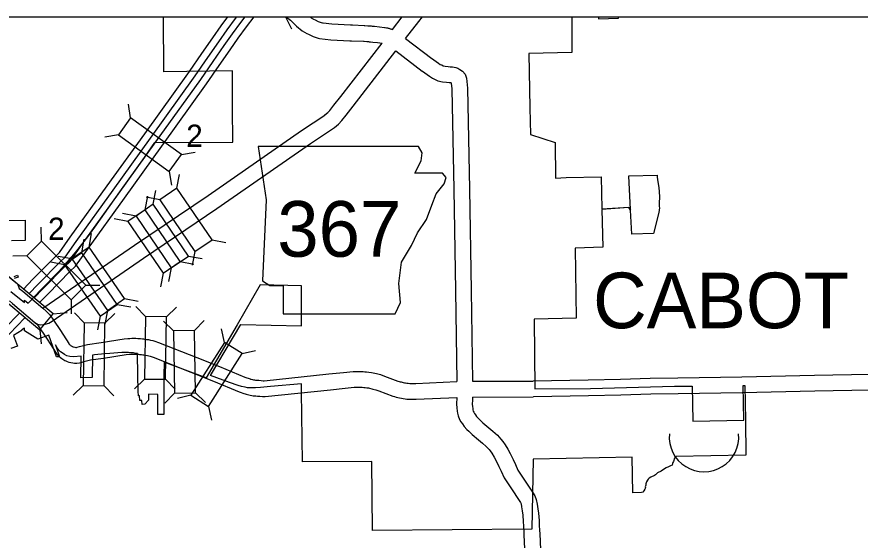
# Model space of a CAD drawing. Extents: x 1127717 to 1741049, y 2026793 to 2244711.
# Drawn here: x 1248173 to 1256180, y 2150676 to 2155644 of the extents above; entities that cross this region are included whole.
import ezdxf

# ---------------------------------------------------------------- set-up
doc = ezdxf.new("R2010")
doc.units = 0
for name, color, linetype in [('1', 7, 'Continuous'), ('10', 7, 'Continuous'), ('15', 7, 'Continuous'), ('20', 7, 'Continuous'), ('21', 7, 'Continuous'), ('27', 7, 'Continuous'), ('6', 7, 'Continuous')]:
    doc.layers.add(name, color=color, linetype=linetype)

msp = doc.modelspace()

# ---------------------------------------------------------------- linework, layer by layer
at = {"layer": '1'}
msp.add_lwpolyline([(1238438.2, 2155644.2), (1269451.6, 2155644.2), (1269451.6, 2123596.1), (1238438.2, 2123596.1)], close=True, dxfattribs=at)
at = {"layer": '10'}
for points in [[(1250731.1, 2155644.2), (1250771.9, 2155611.6), (1250829.6, 2155556.8), (1250881.7, 2155512.8), (1250925.3, 2155487.6), (1250942.3, 2155480.9), (1250967.9, 2155466.4), (1250987.8, 2155457.8), (1251024.9, 2155445), (1251034.8, 2155443.2), (1251046.3, 2155439), (1251153.2, 2155427.6), (1251333.8, 2155418.2), (1251351.4, 2155417.3), (1251463.9, 2155412.4), (1251470, 2155412.1), (1251496.1, 2155410.5), (1251502.7, 2155410), (1251512.5, 2155409.2), (1251518.3, 2155408.7), (1251523.6, 2155408.2), (1251531.2, 2155407.5), (1251551.6, 2155405.3), (1251598.4, 2155400), (1251640.8, 2155395.2)], [(1250958.6, 2155644.2), (1250968.4, 2155636), (1250990.8, 2155623), (1251007, 2155616.6), (1251034.7, 2155600.9), (1251042, 2155597.8), (1251062.9, 2155590.6), (1251074.5, 2155588.5), (1251080.7, 2155586.2), (1251165.1, 2155577.2), (1251341.6, 2155568), (1251358.5, 2155567.1), (1251471, 2155562.2), (1251478.5, 2155561.9), (1251506.4, 2155560.1), (1251514.4, 2155559.5), (1251525, 2155558.7), (1251531.6, 2155558.1), (1251537.6, 2155557.5), (1251546.3, 2155556.7), (1251568, 2155554.4), (1251615.3, 2155549), (1251664.7, 2155543.4), (1251671.5, 2155542.5), (1251683.3, 2155540.6), (1251692.1, 2155538.8), (1251698.3, 2155537.3), (1251705.5, 2155535.4), (1251712.2, 2155533.5), (1251717.4, 2155531.8), (1251723.1, 2155529.8), (1251730.6, 2155527.1), (1251740.1, 2155523.3)], [(1251740.1, 2155523.3), (1251832.4, 2155644.2)], [(1251864.6, 2155439.1), (1251988.3, 2155601.3), (1252023.7, 2155644.2)], [(1248196.2, 2153065.1), (1248228.2, 2153039.6), (1248418.5, 2152877.2), (1248429.7, 2152883.3), (1249291.5, 2153476.2), (1249988.5, 2153949.7), (1250877.3, 2154566), (1251096, 2154711.9), (1251097.6, 2154712.6), (1251125.3, 2154734.7), (1251145.2, 2154756.7), (1251184.1, 2154804.6), (1251249.3, 2154887.3), (1251640.8, 2155395.2)], [(1251864.6, 2155439.1), (1252113, 2155248.8)], [(1248102.5, 2152948), (1248132.6, 2152923.9), (1248344.2, 2152743.5), (1248369.7, 2152728), (1248401.4, 2152721.2), (1248421.9, 2152722.9), (1248441.8, 2152725.3), (1248475.4, 2152737.5), (1248508, 2152755), (1249376.2, 2153352.3), (1250073.3, 2153826), (1250961.6, 2154441.9), (1251188.5, 2154593.3), (1251228.3, 2154624.9), (1251259.1, 2154659), (1251301.2, 2154710.9), (1251367.6, 2154795.1), (1251772.7, 2155320.6)], [(1251772.7, 2155320.6), (1252021.8, 2155129.7)], [(1252110.3, 2155250.8), (1252178, 2155203.7), (1252192.8, 2155193.5), (1252206.9, 2155187.6), (1252222.4, 2155180), (1252241.2, 2155175.2), (1252267.9, 2155172), (1252286.4, 2155170.3), (1252309.4, 2155170.1), (1252340.8, 2155162.5), (1252359.7, 2155155.7), (1252379.7, 2155145.4), (1252405.5, 2155129.6), (1252429.7, 2155100.1), (1252442.9, 2155061.7), (1252447.1, 2155029.6), (1252452.6, 2154967.6), (1252472, 2154007.6), (1252487.4, 2153047.5), (1252499.4, 2152184.6)], [(1252024.6, 2155127.7), (1252092.7, 2155080.4), (1252120.3, 2155061.4), (1252144.6, 2155051.1), (1252170.4, 2155038.4), (1252213.8, 2155027.4), (1252252.2, 2155022.8), (1252278.9, 2155020.4), (1252290.8, 2155020.3), (1252297.2, 2155018.7), (1252297.9, 2155013.4), (1252302.7, 2154959.4), (1252322, 2154004.9), (1252337.5, 2153045.2), (1252349.4, 2152181.2)], [(1247688.1, 2153600.3), (1247695.7, 2153549.9), (1247699, 2153537), (1247702.3, 2153525.6), (1247705.8, 2153516), (1247711, 2153504.3), (1247715.6, 2153495), (1247726.9, 2153475.3), (1247728.4, 2153473), (1247732.8, 2153467.8), (1247766.2, 2153441.1), (1248180.2, 2153109.9), (1248196.2, 2153065.1)], [(1248418.5, 2152877.2), (1248450.3, 2152849.1), (1248461, 2152840.8), (1248486.8, 2152814.4), (1248521.7, 2152763.1)], [(1248348.2, 2152738.5), (1248358.2, 2152730.6), (1248361.3, 2152728.3), (1248370.2, 2152719.1), (1248461.8, 2152584.3), (1248544.9, 2152451.5), (1248555.8, 2152439.3), (1248566.4, 2152427.7), (1248572.7, 2152422.9), (1248577.5, 2152418.4), (1248582.1, 2152414.5), (1248587.4, 2152409.6), (1248600.3, 2152400.1), (1248610.2, 2152394), (1248619.9, 2152388), (1248629.3, 2152382.9), (1248638.5, 2152378), (1248651.7, 2152372.6), (1248666.1, 2152367.4), (1248685.4, 2152362.5), (1248703.1, 2152358.1), (1248721.8, 2152354.9), (1248742.9, 2152355.1), (1248766.8, 2152358.5), (1248785.8, 2152363.3), (1248809.4, 2152370.8), (1248872.4, 2152386.8), (1248994.9, 2152405.3), (1249211.3, 2152437.6), (1249239, 2152440.4), (1249255.9, 2152441.7), (1249272.8, 2152442.5), (1249276.2, 2152442.7), (1249286.6, 2152442.8), (1249296, 2152442.3), (1249312, 2152441.5), (1249326.4, 2152440.5), (1249336.6, 2152439.9), (1249350.1, 2152438.6), (1249357, 2152437.7), (1249368.4, 2152436.3), (1249371.6, 2152436), (1249375.9, 2152435.1), (1249385.1, 2152433.6), (1249395.8, 2152431.8), (1249412.3, 2152428.7), (1249426.6, 2152425.6), (1249438.5, 2152422), (1249468.3, 2152412.5), (1249826.4, 2152272.2), (1250039.5, 2152185.7), (1250284.6, 2152084.8), (1250303.9, 2152077.8), (1250319.1, 2152071.9), (1250328, 2152068.9), (1250340.8, 2152064.2), (1250350.2, 2152061.6), (1250361.6, 2152058.1), (1250374.3, 2152055.4), (1250387.6, 2152051.8), (1250404.7, 2152048.8), (1250415.9, 2152047.6), (1250425.5, 2152046.8), (1250440.7, 2152045.2), (1250457.1, 2152043.9), (1250478.5, 2152041.9), (1250504.9, 2152039.6), (1250530, 2152039.5), (1251151, 2152104.4), (1251290.1, 2152119.1), (1251377, 2152128.2), (1251388.1, 2152128.6), (1251393.6, 2152128.6), (1251406.2, 2152128.5), (1251419, 2152128.6), (1251427.6, 2152128.5), (1251442.4, 2152127.5), (1251452.6, 2152127.1), (1251466.4, 2152126), (1251479.6, 2152125.2), (1251496.5, 2152123.4), (1251511.1, 2152121.4), (1251553.5, 2152111), (1251582.4, 2152104), (1251609.5, 2152093.6), (1251743, 2152044.2), (1251759.8, 2152038.9), (1251773.9, 2152034.6), (1251789.4, 2152031.4), (1251805.4, 2152027.4), (1251823.8, 2152023.2), (1251840, 2152020.6), (1251859.8, 2152017.4), (1251877.4, 2152016.1), (1251891.7, 2152015.1), (1251914.8, 2152013), (1251965.8, 2152014), (1252349.6, 2152031)], [(1248521.7, 2152763.1), (1248587.5, 2152666.2), (1248665.3, 2152541.9), (1248667.2, 2152539.7), (1248667.8, 2152539.1), (1248669.6, 2152537.7), (1248677.3, 2152530.4), (1248681, 2152527.4), (1248682.9, 2152525.6), (1248684.7, 2152524.3), (1248688.7, 2152521.8), (1248695, 2152517.9), (1248700.8, 2152514.8), (1248702.2, 2152514), (1248705.3, 2152512.8), (1248710.2, 2152511), (1248721.9, 2152508), (1248733.2, 2152505.2), (1248737.8, 2152505.9), (1248744.9, 2152507.7), (1248768.2, 2152515.1), (1248842.7, 2152534), (1248972.6, 2152553.6), (1249192.7, 2152586.5), (1249225.5, 2152589.8), (1249246.6, 2152591.4), (1249264.5, 2152592.3), (1249270.8, 2152592.7), (1249289.6, 2152592.8), (1249303.3, 2152592.2), (1249321.4, 2152591.2), (1249336.4, 2152590.1), (1249348.2, 2152589.4), (1249366.8, 2152587.7), (1249375.3, 2152586.6), (1249384.5, 2152585.5), (1249394.6, 2152584.5), (1249403.4, 2152582.6), (1249409.5, 2152581.6), (1249422.2, 2152579.5), (1249442.4, 2152575.7), (1249464.2, 2152570.9), (1249482.9, 2152565.3), (1249518.6, 2152553.9), (1249881.9, 2152411.6), (1250096.2, 2152324.5), (1250338.9, 2152224.7), (1250356.7, 2152218.2), (1250369.9, 2152213.1), (1250377.9, 2152210.4), (1250387, 2152207.1), (1250392.1, 2152205.6), (1250399.3, 2152203.5), (1250409.3, 2152201.3), (1250420.2, 2152198.4), (1250425.8, 2152197.4), (1250430, 2152197), (1250439.8, 2152196.1), (1250454.5, 2152194.5), (1250469.7, 2152193.4), (1250492, 2152191.3), (1250511.7, 2152189.6), (1250522.4, 2152189.5), (1251135.4, 2152253.6), (1251274.4, 2152268.3), (1251366.3, 2152277.9), (1251385.3, 2152278.6), (1251394.4, 2152278.6), (1251406.3, 2152278.5), (1251419.1, 2152278.7), (1251433.7, 2152278.5), (1251450.4, 2152277.3), (1251461.6, 2152276.9), (1251476.9, 2152275.6), (1251492, 2152274.8), (1251514.7, 2152272.3), (1251539.1, 2152269), (1251589.1, 2152256.7), (1251627.2, 2152247.5), (1251662.5, 2152233.9), (1251791.3, 2152186.2), (1251804.1, 2152182.3), (1251811.4, 2152180), (1251822.9, 2152177.6), (1251840.2, 2152173.3), (1251852.4, 2152170.5), (1251863.5, 2152168.7), (1251877.1, 2152166.6), (1251888.6, 2152165.7), (1251903.9, 2152164.6), (1251920.1, 2152163.1), (1251961.1, 2152163.9), (1252349.4, 2152181.2)], [(1258330.4, 2152283.2), (1257618.1, 2152267.8), (1257079.2, 2152261.8), (1256625.1, 2152255.8), (1255746.7, 2152239.1), (1255056.6, 2152225), (1254449.9, 2152214.9), (1254187.4, 2152210.6), (1253903.2, 2152201.1), (1253597.6, 2152195.5), (1253075.4, 2152185.8)], [(1252499.4, 2152184.6), (1253076.7, 2152185.8)], [(1258373.9, 2152134.1), (1257620.5, 2152117.9), (1257081, 2152111.8), (1256627.5, 2152105.8), (1255749.6, 2152089.1), (1255059.4, 2152075), (1254452.3, 2152064.9), (1254191.2, 2152060.6), (1253907.1, 2152051.2), (1253600.4, 2152045.5), (1253078.2, 2152035.8)], [(1252349.6, 2152031), (1252347.7, 2151966.3), (1252349.6, 2151930.9), (1252353.8, 2151901.1), (1252357.2, 2151882.6), (1252363.8, 2151855.2), (1252376.4, 2151823.1), (1252390.1, 2151800.3), (1252404, 2151778.9), (1252421.4, 2151755.6), (1252446.3, 2151726.5), (1252465.4, 2151710.4), (1252495.8, 2151680.1), (1252557.9, 2151626.9), (1252594.7, 2151597.7), (1252629.3, 2151566.5), (1252657.6, 2151535.2), (1252668.5, 2151522.9), (1252682.5, 2151501.5), (1252704.3, 2151464), (1252723.7, 2151430.5), (1252748.7, 2151376.3), (1252770.3, 2151332.1), (1252798.6, 2151268.1), (1252831.7, 2151219.6), (1252869.5, 2151163.7), (1252943.2, 2151052.5), (1252955.1, 2151032.7), (1252960, 2151019.6), (1252966.1, 2150993.3), (1252970.1, 2150954.1), (1252976.3, 2150914.4), (1252981.3, 2150853.3), (1252984.1, 2150808.3), (1252986, 2150762.8), (1252988.2, 2150726.7), (1253014, 2150127.8)], [(1252499.4, 2152034.6), (1252498.9, 2152005.6), (1252497.8, 2151968.1), (1252499, 2151945.4), (1252501.8, 2151925.2), (1252504, 2151913.8), (1252507.2, 2151900.3), (1252511.4, 2151889.7), (1252517.4, 2151879.8), (1252527.2, 2151864.6), (1252538.5, 2151849.4), (1252552.4, 2151833.2), (1252566.9, 2151820.9), (1252597.6, 2151790.3), (1252653.4, 2151742.7), (1252691.7, 2151712.3), (1252735.4, 2151672.8), (1252769.4, 2151635.2), (1252788.2, 2151614.1), (1252810.3, 2151580.1), (1252834, 2151539.3), (1252857, 2151499.6), (1252884.2, 2151440.7), (1252906.3, 2151395.5), (1252930.3, 2151341.3), (1252955.8, 2151303.8), (1252994.2, 2151247.1), (1253069.8, 2151132.8), (1253090.9, 2151098.1), (1253104, 2151062.6), (1253114.3, 2151018), (1253118.9, 2150973.3), (1253125.3, 2150932.1), (1253130.9, 2150864.1), (1253133.9, 2150816.1), (1253135.8, 2150770.5), (1253138, 2150734.5), (1253163.8, 2150134.4)], [(1252499.4, 2152034.6), (1253077, 2152035.8)]]:
    msp.add_lwpolyline(points, dxfattribs=at)
at = {"layer": '15'}
for points in [[(1248235.1, 2153060.1), (1248325.6, 2153154.5), (1248536.1, 2153366.9), (1248577.9, 2153408.2), (1248680.5, 2153552.3), (1249031.7, 2154039.8), (1249387.6, 2154534.1), (1249811.3, 2155124), (1249928.4, 2155296.1), (1250033.7, 2155446.4), (1250113.2, 2155560.2), (1250175.2, 2155644.2)], [(1248288, 2153016), (1248374.8, 2153106.5), (1248584.7, 2153318.3), (1248630.4, 2153363.5), (1248736.4, 2153512.3), (1249087.5, 2153999.6), (1249443.4, 2154494), (1249867.6, 2155084.6), (1249985, 2155257), (1250090.1, 2155407), (1250169, 2155520.1), (1250248.3, 2155627.5), (1250261.2, 2155644.2)], [(1248336.2, 2152975.9), (1248419.5, 2153062.9), (1248628.9, 2153274.1), (1248678.2, 2153322.9), (1248787.2, 2153475.9), (1249138.2, 2153963.1), (1249494.1, 2154457.5), (1249918.9, 2155048.8), (1250036.5, 2155221.5), (1250141.3, 2155371.2), (1250219.8, 2155483.6), (1250298.2, 2155589.8), (1250340.2, 2155644.2)], [(1248389.1, 2152931.8), (1248468.8, 2153014.9), (1248677.5, 2153225.4), (1248730.8, 2153278.2), (1248843.1, 2153435.9), (1249194, 2153922.9), (1249550, 2154417.4), (1249975.2, 2155009.4), (1250093, 2155182.5), (1250197.6, 2155331.8), (1250275.6, 2155443.5), (1250353, 2155548.3), (1250427.1, 2155644.2)], [(1247604.1, 2152222.1), (1248053.9, 2152683), (1248199.8, 2152834)], [(1247605.7, 2152125.3), (1248103.2, 2152635.1), (1248250, 2152787)]]:
    msp.add_lwpolyline(points, dxfattribs=at)
at = {"layer": '20'}
for p, q in [((1250723.2, 2155644.2), (1250779.6, 2155531.3)), ((1249253.1, 2154684.5), (1249231.9, 2154814.8)), ((1249137.4, 2154523.8), (1249007.1, 2154502.6)), ((1249735.1, 2154337.4), (1249865.4, 2154358.6)), ((1249619.5, 2154176.7), (1249640.7, 2154046.5)), ((1249693.5, 2154017.7), (1249718.2, 2154147.3)), ((1249391.1, 2153812.2), (1249415.9, 2153941.9)), ((1249529.7, 2153906.4), (1249400.1, 2153931.1)), ((1249468.3, 2153864.7), (1249493.1, 2153994.3)), ((1249304.6, 2153753.4), (1249174.9, 2153778.2)), ((1249227.4, 2153700.9), (1249097.7, 2153725.7)), ((1248405.5, 2153515), (1248404.9, 2153647)), ((1248789.2, 2153403.6), (1248813.2, 2153533.4)), ((1248858.5, 2153458.6), (1248882.5, 2153588.4)), ((1250027.3, 2153526.3), (1250157, 2153501.6)), ((1248266.1, 2153374.3), (1248134.1, 2153373.8)), ((1248695.4, 2153346.4), (1248565.6, 2153370.4)), ((1249802.2, 2153373.4), (1249931.8, 2153348.6)), ((1249863.5, 2153415.1), (1249838.8, 2153285.4)), ((1248626, 2153291.4), (1248496.2, 2153315.4)), ((1249724.9, 2153320.9), (1249854.6, 2153296.1)), ((1249561.2, 2153209.6), (1249536.4, 2153080)), ((1249638.4, 2153262.1), (1249613.6, 2153132.4)), ((1248827.4, 2153096.8), (1248959.4, 2153097.4)), ((1249195.2, 2152969.3), (1249325, 2152945.3)), ((1248688, 2152956.2), (1248688.6, 2152824.2)), ((1249125.8, 2152914.2), (1249255.6, 2152890.2)), ((1249395.1, 2152799.9), (1249303.2, 2152894.6)), ((1249593.1, 2152796.9), (1249687.8, 2152888.8)), ((1248518.7, 2152823.9), (1248650.1, 2152835.9)), ((1248811.6, 2152738.8), (1248719.7, 2152833.5)), ((1249032.1, 2152857), (1249008.1, 2152727.2)), ((1249009.6, 2152735.7), (1249104.4, 2152827.6)), ((1248962.7, 2152802), (1248938.7, 2152672.2)), ((1249661.5, 2152664.3), (1249566.8, 2152756.3)), ((1249859.5, 2152667.3), (1249951.4, 2152762.1)), ((1248392, 2152671.7), (1248403.9, 2152540.3)), ((1250143.9, 2152552.7), (1250115.1, 2152681.6)), ((1250311.1, 2152446.7), (1250439.9, 2152475.5)), ((1249386.2, 2152205.9), (1249291.5, 2152114)), ((1249584.2, 2152203), (1249676.1, 2152108.3)), ((1248802.4, 2152144.8), (1248707.7, 2152053)), ((1249000.4, 2152141.8), (1249092.3, 2152047)), ((1249670.5, 2152070.4), (1249578.6, 2151975.7)), ((1249825.8, 2152051.1), (1249697, 2152022.3)), ((1249868.5, 2152073.4), (1249963.2, 2151981.5)), ((1249993, 2151945.1), (1250021.8, 2151816.3))]:
    msp.add_line(p, q, dxfattribs=at)
for points in [[(1249137.4, 2154523.8), (1249619.5, 2154176.7), (1249735.1, 2154337.4), (1249253.1, 2154684.5)], [(1249529.7, 2153906.4), (1249863.5, 2153415.1), (1250027.3, 2153526.3), (1249693.5, 2154017.7)], [(1249304.6, 2153753.4), (1249638.4, 2153262.1), (1249802.2, 2153373.4), (1249468.3, 2153864.7)], [(1249724.9, 2153320.9), (1249391.1, 2153812.2), (1249227.4, 2153700.9), (1249561.2, 2153209.6)], [(1248827.4, 2153096.8), (1248405.5, 2153515), (1248266.1, 2153374.3), (1248688, 2152956.2)], [(1249195.2, 2152969.3), (1248858.5, 2153458.6), (1248695.4, 2153346.4), (1249032.1, 2152857)], [(1248626, 2153291.4), (1248962.7, 2152802), (1249125.8, 2152914.2), (1248789.2, 2153403.6)], [(1247935.6, 2153051.9), (1248392, 2152671.7), (1248518.7, 2152823.9), (1248062.3, 2153204.1)], [(1249000.4, 2152141.8), (1249009.6, 2152735.7), (1248811.6, 2152738.8), (1248802.4, 2152144.8)], [(1249395.1, 2152799.9), (1249386.2, 2152205.9), (1249584.2, 2152203), (1249593.1, 2152796.9)], [(1249661.5, 2152664.3), (1249670.5, 2152070.4), (1249868.5, 2152073.4), (1249859.5, 2152667.3)], [(1250143.9, 2152552.7), (1249825.8, 2152051.1), (1249993, 2151945.1), (1250311.1, 2152446.7)]]:
    msp.add_lwpolyline(points, close=True, dxfattribs=at)
at = {"layer": '21'}
msp.add_lwpolyline([(1250463.9, 2154413.9), (1250540, 2153906.4), (1250506.2, 2153136.6), (1250573.9, 2153094.3), (1250700.7, 2153094.3), (1250700.7, 2152823.6), (1251766.6, 2152823.6), (1251817.3, 2152933.6), (1251800.4, 2153111.2), (1251825.8, 2153314.2), (1251918.8, 2153475), (1251978, 2153593.4), (1252062.6, 2153720.3), (1252113.4, 2153855.6), (1252155.7, 2153965.6), (1252231.8, 2154058.6), (1252248.7, 2154117.8), (1252214.9, 2154160.1), (1251952.7, 2154160.1), (1252011.9, 2154278.6), (1252020.3, 2154354.7), (1251985.3, 2154413.2)], close=True, dxfattribs=at)
at = {"layer": '27'}
msp.add_arc((1254697.3, 2151654.4), 330, 174.81174, 5.18826, dxfattribs=at)
at = {"layer": '6'}
for points in [[(1248115.5, 2153036.4), (1248246.3, 2152931.1), (1248246.5, 2152953.3), (1248280.7, 2152927.5), (1248403, 2153057.3), (1248568.2, 2153222.5), (1248628.9, 2153289.9), (1248696.3, 2153365.2), (1248742.6, 2153421.9), (1248848.3, 2153555.2), (1248912.9, 2153647.7), (1249151.3, 2153983.2), (1249384.2, 2154309.9), (1249484.4, 2154451.5), (1250223.1, 2154455.2), (1250221, 2154785.1), (1250219.6, 2155130.8), (1249568, 2155123.2), (1249566.5, 2155644.2)], [(1253441.2, 2155644.2), (1253443.6, 2155306.1), (1253035.6, 2155296.6), (1253042.9, 2154779.1)], [(1253695.1, 2155644.2), (1253695.3, 2155625.9)], [(1253695.3, 2155625.9), (1253886.3, 2155630.3), (1253886.7, 2155644.2)], [(1253042.9, 2154779.1), (1253049.3, 2154528.8), (1253285.3, 2154450.3), (1253286.1, 2154113.4), (1253390.4, 2154117.7), (1253720.9, 2154126.7), (1253728.9, 2153820.6), (1253984.2, 2153838), (1253999.9, 2153815.9), (1253985.1, 2154133.9), (1254251.7, 2154141.1), (1254252.2, 2154122), (1254260.5, 2154078.5), (1254268.7, 2154024.5), (1254271.4, 2153982.2), (1254273.8, 2153934.2), (1254272.8, 2153876.4), (1254273, 2153843.1), (1254273.8, 2153830.6), (1254268.2, 2153787), (1254219.3, 2153587.7), (1254010.8, 2153580.6), (1254000.2, 2153808.9), (1253982.3, 2153834.1), (1253729, 2153816.8), (1253738.5, 2153457.4), (1253472.8, 2153449.7), (1253483.1, 2152784.6), (1253083.4, 2152774.9), (1253089.9, 2152111.5), (1253621.1, 2152114.6), (1254416.9, 2152137.4), (1254584.2, 2152139), (1254590.1, 2151806.6), (1255075.6, 2151814.3), (1255071, 2152145.4), (1255086, 2152145.6), (1255090.6, 2151814.5), (1255095.1, 2151482.3), (1254429.6, 2151470.5), (1254429.8, 2151463.3), (1254423.9, 2151460.9), (1254416.8, 2151455.7), (1254408, 2151421.6), (1254401, 2151414), (1254397.4, 2151404.6), (1254394.5, 2151388.7), (1254381, 2151381.1), (1254360.4, 2151371.7), (1254338.1, 2151363.5), (1254322.3, 2151354.1), (1254290, 2151331.8), (1254256.5, 2151314.1), (1254237.1, 2151297.7), (1254226.6, 2151291.2), (1254191.9, 2151274.8), (1254176.7, 2151264.2), (1254167.3, 2151254.8), (1254159.6, 2151246.6), (1254151.4, 2151230.2), (1254146.1, 2151211.4), (1254144.9, 2151197.3), (1254139.7, 2151182.6), (1254140.8, 2151171.5), (1254136.7, 2151160.9), (1254126.2, 2151143.3), (1254117.9, 2151132.7), (1254102.7, 2151128.6), (1254023.4, 2151126.3), (1254017.1, 2151462.9), (1253074.4, 2151445.6), (1253061.3, 2150779.5)], [(1247923.9, 2153710.1), (1248253, 2153713.2), (1248252.3, 2153520.3), (1248121.6, 2153517.2)], [(1248146.4, 2153178.7), (1248177.8, 2153190.4), (1248183.8, 2153173.9), (1248146.1, 2153160)], [(1253061.3, 2150779.5), (1251549.6, 2150768.4), (1251545, 2151424), (1250884.8, 2151420.5), (1250875.3, 2152084.3), (1250875.2, 2152161.4), (1250580.6, 2152133.6), (1250485, 2152123.8), (1250440.4, 2152121.1), (1250410.3, 2152121.1), (1250392.7, 2152120.6), (1250377.8, 2152121.5), (1250363.9, 2152123.4), (1250341.2, 2152127.1), (1250305, 2152135.4), (1250273.4, 2152144.3), (1250192.7, 2152172.6), (1250010.5, 2152238.2), (1250299.4, 2152722.7), (1250874.8, 2152709.8), (1250874.5, 2153089.3), (1250482.8, 2153101.1), (1250264.7, 2152721.5), (1249970, 2152216.9), (1249800.3, 2152281.6), (1249571.1, 2152365.3), (1249567.6, 2152240.8), (1249568.2, 2152089.1), (1249568.2, 2151868.3), (1249510.1, 2151869.3), (1249512.4, 2152060.2), (1249422, 2152061.8), (1249421.5, 2152004.2), (1249387.3, 2151967.5), (1249363.9, 2151965), (1249360.1, 2152002.3), (1249340.1, 2152000.5), (1249338.1, 2152047.5), (1249326.9, 2152047.1), (1249326.1, 2152089.1), (1249323, 2152240.9), (1249317.2, 2152446.8), (1249303.9, 2152449.5), (1249281, 2152453.4), (1249256.2, 2152456), (1249233.6, 2152457.8), (1249204.1, 2152459), (1249168.5, 2152458.1), (1249054.8, 2152447.8), (1249007.2, 2152444.2), (1248909.4, 2152434.8), (1248891.8, 2152433), (1248886.8, 2152220.2), (1248780.2, 2152218.4), (1248784.8, 2152422.8), (1248709.7, 2152416.8), (1248677.4, 2152420.6), (1248649, 2152426.8), (1248626.7, 2152437.5), (1248602.9, 2152453.7), (1248585.9, 2152464.4), (1248572.1, 2152479.8), (1248556, 2152502.8), (1248540.8, 2152530.8), (1248577.7, 2152417.3), (1248550.7, 2152416.9), (1248476.4, 2152622.4), (1248370.8, 2152584.7), (1248244.6, 2152661.9), (1248244.7, 2152687.8), (1248221, 2152672.4), (1248222.3, 2152670.2), (1248142, 2152617.7), (1248178.7, 2152516.9), (1248116.7, 2152496.1)]]:
    msp.add_lwpolyline(points, dxfattribs=at)

# ---------------------------------------------------------------- texts
at = {"layer": '20'}
for p in [(1249780.9, 2154409.9), (1248469, 2153527)]:
    msp.add_text('2', height=211.2, dxfattribs=at).set_placement(p)
at = {"layer": '21'}
msp.add_text('367', height=528, dxfattribs=at).set_placement((1250645.6, 2153367.2))
at = {"layer": '6'}
msp.add_text('CABOT', height=528, dxfattribs=at).set_placement((1253644, 2152688.1))

doc.saveas('drawing.dxf')
